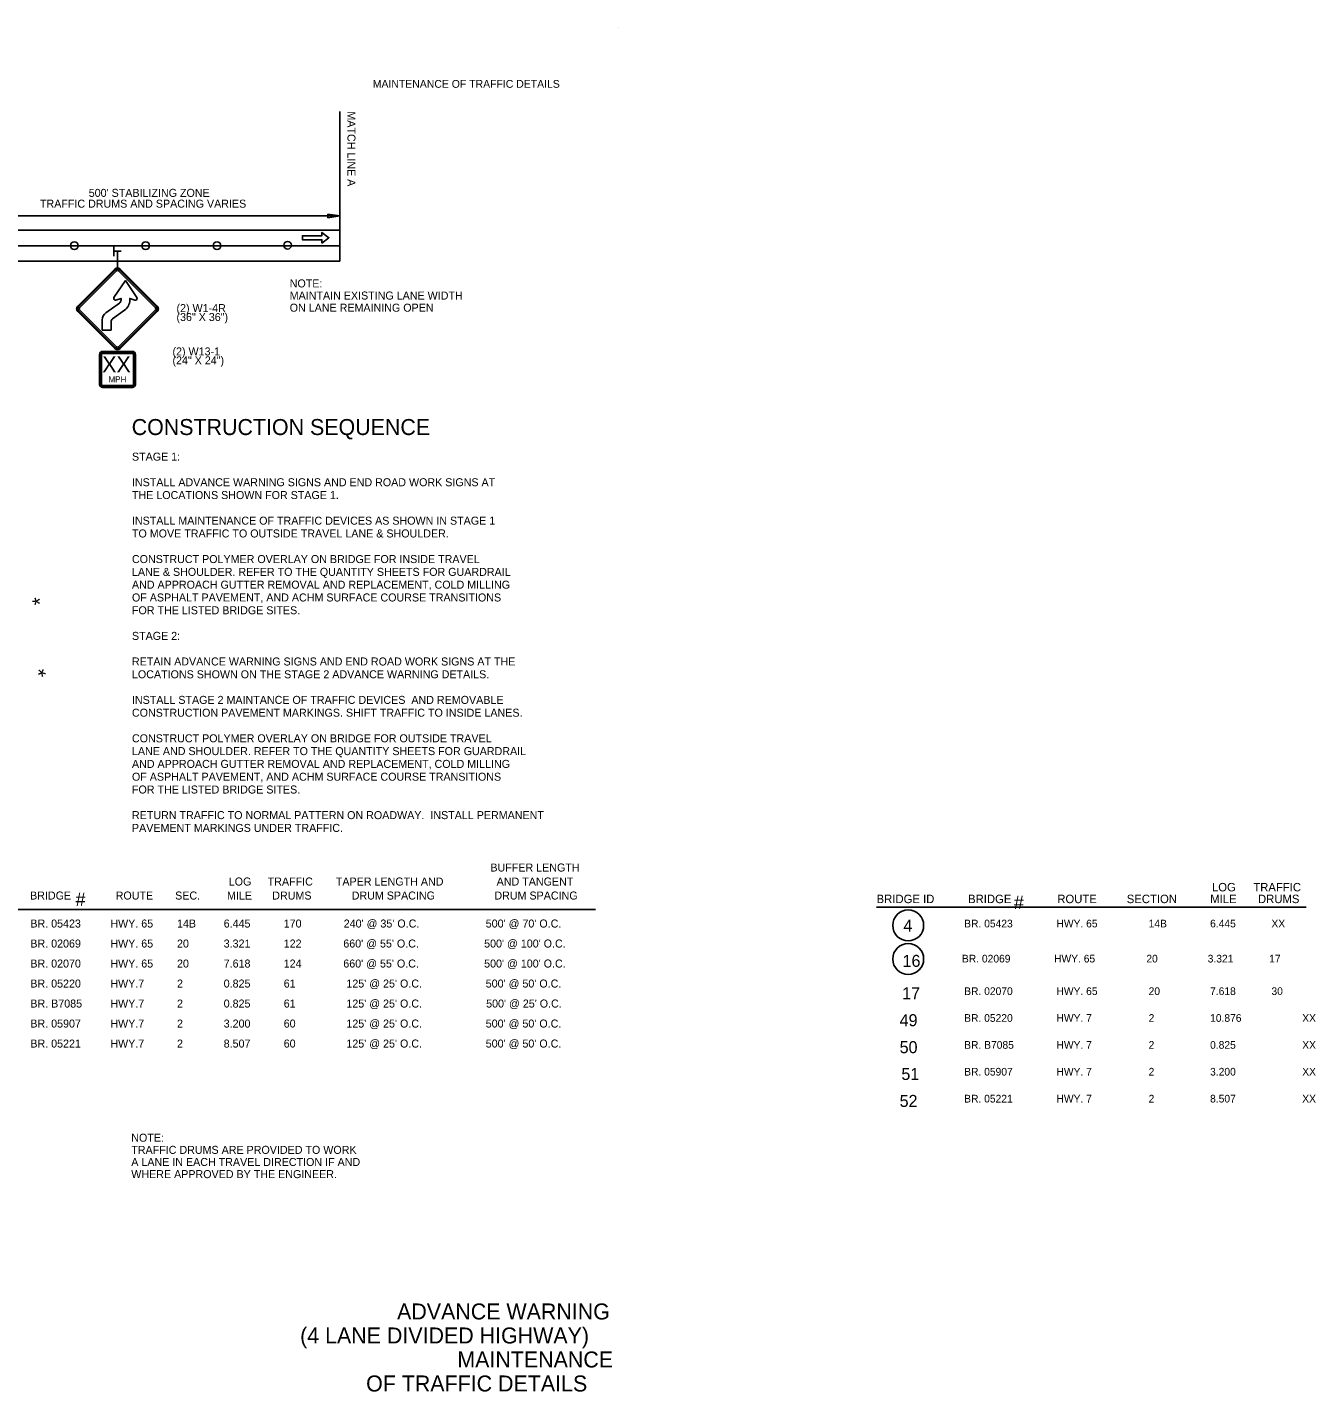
# Model space of a CAD drawing. Extents: x 1930579 to 1938745, y 596452 to 597559.
# Drawn here: x 1937779 to 1938745, y 596536 to 597559 of the extents above; entities that cross this region are included whole.
import ezdxf

# ---------------------------------------------------------------- set-up
doc = ezdxf.new("R2010")
doc.units = 0
for name, color, linetype in [('Default', 7, 'Continuous'), ('P_TC_Signs_Permanent', 7, 'Continuous'), ('R_Annotation', 7, 'Continuous'), ('R_Border', 7, 'Continuous'), ('R_Striping', 7, 'Continuous')]:
    doc.layers.add(name, color=color, linetype=linetype)

msp = doc.modelspace()

# ---------------------------------------------------------------- linework, layer by layer
at = {"layer": 'Default'}
for p, q in [((1938013.5, 597495.8), (1938013.5, 597383.6)), ((1938013.5, 597417.4), (1937761.7, 597417.4)), ((1938004.6, 597416.1), (1938004.6, 597418.8)), ((1938004.6, 597418.8), (1938013.5, 597417.4)), ((1938013.5, 597417.4), (1938004.6, 597416.1)), ((1938013.5, 597406.7), (1937394.5, 597406.7)), ((1938013.5, 597395.1), (1936726.8, 597395.1)), ((1937844, 597387.2), (1937844, 597395.1)), ((1938013.5, 597383.6), (1937394.5, 597383.6)), ((1937844.2, 597391.1), (1937849.6, 597391.1))]:
    msp.add_line(p, q, dxfattribs=at)
for centre, radius in [((1937814.5, 597395.1), 2.87), ((1937868, 597395.1), 2.87), ((1937921.5, 597395.1), 2.87), ((1937974.4, 597395.4), 2.87), ((1938439.8, 596885.4), 11.6), ((1938439.8, 596860.2), 11.6)]:
    msp.add_circle(centre, radius, dxfattribs=at)
at = {"layer": 'P_TC_Signs_Permanent'}
for p, q in [((1937817.1, 597349.8), (1937844.9, 597377.6)), ((1937817.6, 597349.2), (1937845.4, 597377.1)), ((1937846.2, 597376.3), (1937818.4, 597348.4)), ((1937875.4, 597348.4), (1937847.6, 597376.3)), ((1937848.3, 597377.1), (1937876.2, 597349.2)), ((1937848.9, 597377.6), (1937876.7, 597349.8)), ((1937838.1, 597344.7), (1937848.3, 597352.1)), ((1937844.9, 597318), (1937817.1, 597345.8)), ((1937845.4, 597318.5), (1937817.6, 597346.3)), ((1937818.4, 597347.1), (1937846.2, 597319.3)), ((1937852.2, 597346.7), (1937843.1, 597340.2)), ((1937847.6, 597319.3), (1937875.4, 597347.1)), ((1937876.2, 597346.3), (1937848.3, 597318.5)), ((1937876.7, 597345.8), (1937848.9, 597318)), ((1937833.4, 597313.6), (1937833.4, 597291.1)), ((1937834, 597313.6), (1937834, 597291.1)), ((1937834.9, 597313.6), (1937834.9, 597291.1)), ((1937858.1, 597315.8), (1937835.6, 597315.8)), ((1937858.1, 597315.3), (1937835.6, 597315.3)), ((1937858.1, 597314.3), (1937835.6, 597314.3)), ((1937858.9, 597291.1), (1937858.9, 597313.6)), ((1937859.8, 597291.1), (1937859.8, 597313.6)), ((1937860.4, 597291.1), (1937860.4, 597313.6)), ((1937835.6, 597290.3), (1937858.1, 597290.3)), ((1937835.6, 597289.4), (1937858.1, 597289.4)), ((1937835.6, 597288.8), (1937858.1, 597288.8))]:
    msp.add_line(p, q, dxfattribs=at)
for points in [[(1937844.2, 597356.3), (1937852.8, 597368.9), (1937861.4, 597356.3)], [(1937849.5, 597354.3), (1937849.5, 597355.5), (1937845.7, 597354.3)], [(1937859.9, 597354.3), (1937856.1, 597355.5), (1937856.1, 597354.3)], [(1937842, 597337.9), (1937842, 597331.8), (1937835.4, 597331.8), (1937835.4, 597339.4)]]:
    msp.add_lwpolyline(points, dxfattribs=at)
for centre, radius, start, end in [((1937846.9, 597375.6), 2.81, 45, 135), ((1937846.9, 597375.6), 2.06, 45, 135), ((1937846.9, 597375.6), 0.937, 45, 135), ((1937845.3, 597355.6), 1.31, 145.6763, 287.8128), ((1937846.7, 597354.3), 2.81, 305.7733, 0), ((1937846.7, 597354.3), 9.37, 305.7733, 0), ((1937860.3, 597355.6), 1.31, 252.1872, 34.3237), ((1937819, 597347.8), 2.81, 135, 225), ((1937819, 597347.8), 2.06, 135, 225), ((1937819, 597347.8), 0.937, 135, 225), ((1937842, 597339.4), 6.56, 125.7733, 180), ((1937844.8, 597337.9), 2.81, 125.7733, 180), ((1937874.7, 597347.8), 0.937, 315, 45), ((1937874.7, 597347.8), 2.06, 315, 45), ((1937874.7, 597347.8), 2.81, 315, 45), ((1937835.6, 597313.6), 2.25, 90, 180), ((1937835.6, 597313.6), 1.69, 90, 180), ((1937835.6, 597313.6), 0.75, 90, 180), ((1937846.9, 597319.9), 2.81, 225, 315), ((1937846.9, 597319.9), 2.06, 225, 315), ((1937846.9, 597319.9), 0.937, 225, 315), ((1937858.1, 597313.6), 2.25, 360, 90), ((1937858.1, 597313.6), 1.69, 360, 90), ((1937858.1, 597313.6), 0.75, 360, 90), ((1937835.6, 597291.1), 2.25, 180, 270), ((1937835.6, 597291.1), 1.69, 180, 270), ((1937835.6, 597291.1), 0.75, 180, 270), ((1937858.1, 597291.1), 2.25, 270, 360), ((1937858.1, 597291.1), 1.69, 270, 360), ((1937858.1, 597291.1), 0.75, 270, 360)]:
    msp.add_arc(centre, radius, start, end, dxfattribs=at)
at = {"layer": 'R_Annotation'}
for p, q in [((1937846.9, 597391.1), (1937846.9, 597378.4)), ((1937728.1, 596897.3), (1938205.3, 596897.3)), ((1938416.1, 596899.2), (1938738.3, 596899.2))]:
    msp.add_line(p, q, dxfattribs=at)
at = {"layer": 'R_Border'}
msp.add_line((1938222.3, 597558.9), (1938222.3, 597558.9), dxfattribs=at)
at = {"layer": 'R_Striping'}
msp.add_lwpolyline([(1938000.2, 597397), (1938005.4, 597401), (1938000.2, 597405), (1938000.2, 597402.5), (1937985.5, 597402.5), (1937985.5, 597399.5), (1938000.2, 597399.5)], close=True, dxfattribs=at)

# ---------------------------------------------------------------- texts
at = {"layer": 'Default'}
for s, rotation, p in [('MATCH LINE A', 270, (1938019.3, 597495.8)), ("500' STABILIZING ZONE", 360, (1937825.3, 597431.7)), ('TRAFFIC DRUMS AND SPACING VARIES', 360, (1937788.7, 597423.6))]:
    msp.add_text(s, height=6, rotation=rotation, dxfattribs=at).set_placement(p)
at = {"layer": 'P_TC_Signs_Permanent'}
for s, height, p in [('XX', 12, (1937835.4, 597300.1)), ('MPH', 4.5, (1937840.1, 597292.6))]:
    msp.add_text(s, height=height, rotation=360, dxfattribs=at).set_placement(p)
at = {"layer": 'R_Annotation'}
for s, height, rotation, p in [('NOTE:', 6, 360, (1937976, 597363.8)), ('MAINTAIN EXISTING LANE WIDTH ', 6, 360, (1937976, 597354.7)), ('(2) W1-4R', 6, 360, (1937891.1, 597345.3)), ('ON LANE REMAINING OPEN', 6, 360, (1937976, 597345.6)), ('(36" X 36")', 6, 360, (1937891.1, 597338.6)), ('(2) W13-1', 6, 360, (1937888.1, 597312.8)), ('(24" X 24")', 6, 360, (1937888.1, 597306.1)), ('CONSTRUCTION SEQUENCE', 12, 360, (1937857.5, 597253.1)), ('STAGE 1:', 6, 360, (1937857.7, 597233.9)), ('INSTALL ADVANCE WARNING SIGNS AND END ROAD WORK SIGNS AT', 6, 360, (1937857.7, 597214.7)), ('THE LOCATIONS SHOWN FOR STAGE 1.', 6, 360, (1937857.7, 597205.1)), ('INSTALL MAINTENANCE OF TRAFFIC DEVICES AS SHOWN IN STAGE 1', 6, 360, (1937857.7, 597185.9)), ('TO MOVE TRAFFIC TO OUTSIDE TRAVEL LANE & SHOULDER.', 6, 360, (1937857.7, 597176.3)), ('CONSTRUCT POLYMER OVERLAY ON BRIDGE FOR INSIDE TRAVEL', 6, 360, (1937857.7, 597157.1)), ('LANE & SHOULDER. REFER TO THE QUANTITY SHEETS FOR GUARDRAIL', 6, 360, (1937857.7, 597147.5)), ('AND APPROACH GUTTER REMOVAL AND REPLACEMENT, COLD MILLING', 6, 360, (1937857.7, 597137.9)), ('*', 11.5, 90.312, (1937794.4, 597125.5)), ('OF ASPHALT PAVEMENT, AND ACHM SURFACE COURSE TRANSITIONS', 6, 360, (1937857.7, 597128.3)), ('FOR THE LISTED BRIDGE SITES.', 6, 360, (1937857.7, 597118.7)), ('STAGE 2:', 6, 360, (1937857.7, 597099.5)), ('RETAIN ADVANCE WARNING SIGNS AND END ROAD WORK SIGNS AT THE', 6, 360, (1937857.7, 597080.3)), ('*', 11.5, 45, (1937793.9, 597066.7)), ('LOCATIONS SHOWN ON THE STAGE 2 ADVANCE WARNING DETAILS.', 6, 360, (1937857.7, 597070.7)), ('INSTALL STAGE 2 MAINTANCE OF TRAFFIC DEVICES  AND REMOVABLE', 6, 360, (1937857.7, 597051.5)), ('CONSTRUCTION PAVEMENT MARKINGS. SHIFT TRAFFIC TO INSIDE LANES.', 6, 360, (1937857.7, 597041.9)), ('CONSTRUCT POLYMER OVERLAY ON BRIDGE FOR OUTSIDE TRAVEL', 6, 360, (1937857.7, 597022.7)), ('LANE AND SHOULDER. REFER TO THE QUANTITY SHEETS FOR GUARDRAIL', 6, 360, (1937857.7, 597013.1)), ('AND APPROACH GUTTER REMOVAL AND REPLACEMENT, COLD MILLING', 6, 360, (1937857.7, 597003.5)), ('OF ASPHALT PAVEMENT, AND ACHM SURFACE COURSE TRANSITIONS', 6, 360, (1937857.7, 596993.9)), ('FOR THE LISTED BRIDGE SITES.', 6, 360, (1937857.7, 596984.3)), ('RETURN TRAFFIC TO NORMAL PATTERN ON ROADWAY.  INSTALL PERMANENT', 6, 360, (1937857.7, 596965.1)), ('PAVEMENT MARKINGS UNDER TRAFFIC.', 6, 360, (1937857.7, 596955.5)), ('LOG', 6, 360, (1937930.3, 596915.3)), ('TRAFFIC', 6, 360, (1937959.5, 596915.3)), ('TAPER LENGTH AND', 6, 360, (1938010.6, 596915.3)), ('BRIDGE', 6, 360, (1937781.3, 596904.8)), ('ROUTE', 6, 360, (1937845.5, 596904.8)), ('SEC.', 6, 360, (1937890.1, 596904.8)), ('MILE', 6, 360, (1937929, 596904.8)), ('DRUMS', 6, 360, (1937962.9, 596904.8)), ('DRUM SPACING', 6, 360, (1938022.5, 596904.8)), ('LOG', 6.34, 360, (1938667.6, 596910.9)), ('TRAFFIC', 6.34, 360, (1938698.6, 596910.9)), ('#', 10.1, 360, (1937815.4, 596899.9)), ('BRIDGE ID', 6.34, 360, (1938416.1, 596902.1)), ('BRIDGE ', 6.34, 360, (1938484.7, 596902.1)), ('#', 10.1, 360, (1938519, 596897.6)), ('ROUTE', 6.34, 360, (1938551.6, 596902.1)), ('SECTION', 6.34, 360, (1938603.7, 596902.1)), ('MILE', 6.34, 360, (1938666.3, 596902.1)), ('DRUMS', 6.34, 360, (1938702.1, 596902.1)), ('BR. 05423', 6, 360, (1937781.5, 596883.8)), ('HWY. 65', 6, 360, (1937841.5, 596883.8)), ('170', 6, 360, (1937971.5, 596883.8)), ("240' @ 35' O.C.", 6, 360, (1938016.5, 596883.8)), ('14B', 6, 360, (1937891.5, 596883.8)), ('4', 9, 360, (1938436.2, 596880.7)), ('BR. 05423', 5.76, 360, (1938481.8, 596883.9)), ('HWY. 65', 5.76, 360, (1938551, 596883.9)), ('14B', 5.76, 360, (1938620.1, 596883.9)), ('6.445', 5.76, 360, (1938666.2, 596883.9)), ('XX', 5.76, 360, (1938712.2, 596883.9)), ('BR. 02069', 6, 360, (1937781.5, 596868.8)), ('HWY. 65', 6, 360, (1937841.5, 596868.8)), ('20', 6, 360, (1937891.5, 596868.8)), ('122', 6, 360, (1937971.5, 596868.8)), ("660' @ 55' O.C.", 6, 360, (1938016.2, 596868.8)), ('BR. 02070', 6, 360, (1937781.5, 596853.8)), ('HWY. 65', 6, 360, (1937841.5, 596853.8)), ('20', 6, 360, (1937891.5, 596853.8)), ('124', 6, 360, (1937971.5, 596853.8)), ("660' @ 55' O.C.", 6, 360, (1938016.2, 596853.8)), ('16', 9, 360, (1938435.6, 596854.3)), ('BR. 02069', 5.76, 360, (1938480.1, 596857.6)), ('HWY. 65', 5.76, 360, (1938549.2, 596857.6)), ('20', 5.76, 360, (1938618.4, 596857.6)), ('3.321', 5.76, 360, (1938664.4, 596857.6)), ('17', 5.76, 360, (1938710.5, 596857.6)), ('BR. 05220', 6, 360, (1937781.5, 596838.8)), ('HWY.7', 6, 360, (1937841.5, 596838.8)), ('2', 6, 360, (1937891.5, 596838.8)), ('61', 6, 360, (1937971.5, 596838.8)), ("125' @ 25' O.C.", 6, 360, (1938018.5, 596838.8)), ('17', 9, 360, (1938435.3, 596830)), ('BR. 02070', 5.76, 360, (1938481.8, 596833.2)), ('HWY. 65', 5.76, 360, (1938551, 596833.2)), ('20', 5.76, 360, (1938620.1, 596833.2)), ('7.618', 5.76, 360, (1938666.2, 596833.2)), ('30', 5.76, 360, (1938712.2, 596833.2)), ('BR. B7085', 6, 360, (1937781.5, 596823.8)), ('HWY.7', 6, 360, (1937841.5, 596823.8)), ('2', 6, 360, (1937891.5, 596823.8)), ('61', 6, 360, (1937971.5, 596823.8)), ("125' @ 25' O.C.", 6, 360, (1938018.5, 596823.8)), ('49', 9, 360, (1938433.4, 596809.8)), ('BR. 05220', 5.76, 360, (1938481.8, 596813.1)), ('HWY. 7', 5.76, 360, (1938551, 596813.1)), ('2', 5.76, 360, (1938620.1, 596813.1)), ('10.876', 5.76, 360, (1938666.2, 596813.1)), ('XX', 5.76, 360, (1938735.3, 596813.1)), ('BR. 05907', 6, 360, (1937781.5, 596808.8)), ('HWY.7', 6, 360, (1937841.5, 596808.8)), ('2', 6, 360, (1937891.5, 596808.8)), ('60', 6, 360, (1937971.5, 596808.8)), ("125' @ 25' O.C.", 6, 360, (1938018.5, 596808.8)), ('BR. 05221', 6, 360, (1937781.5, 596793.8)), ('HWY.7', 6, 360, (1937841.5, 596793.8)), ('2', 6, 360, (1937891.5, 596793.8)), ('60', 6, 360, (1937971.5, 596793.8)), ("125' @ 25' O.C.", 6, 360, (1938018.5, 596793.8)), ('50', 9, 360, (1938433.4, 596789.6)), ('BR. B7085', 5.76, 360, (1938481.8, 596792.9)), ('HWY. 7', 5.76, 360, (1938551, 596792.9)), ('2', 5.76, 360, (1938620.1, 596792.9)), ('0.825', 5.76, 360, (1938666.2, 596792.9)), ('XX', 5.76, 360, (1938735.3, 596792.9)), ('51', 9, 360, (1938434.7, 596769.5)), ('BR. 05907', 5.76, 360, (1938481.8, 596772.8)), ('HWY. 7', 5.76, 360, (1938551, 596772.8)), ('2', 5.76, 360, (1938620.1, 596772.8)), ('3.200', 5.76, 360, (1938666.2, 596772.8)), ('XX', 5.76, 360, (1938735.3, 596772.8)), ('52', 9, 360, (1938433.4, 596749.3)), ('BR. 05221', 5.76, 360, (1938481.8, 596752.6)), ('HWY. 7', 5.76, 360, (1938551, 596752.6)), ('2', 5.76, 360, (1938620.1, 596752.6)), ('8.507', 5.76, 360, (1938666.2, 596752.6)), ('XX', 5.76, 360, (1938735.3, 596752.6)), ('NOTE:', 6, 360, (1937857.2, 596723.2)), ('TRAFFIC DRUMS ARE PROVIDED TO WORK', 6, 360, (1937857.2, 596714.1)), ('A LANE IN EACH TRAVEL DIRECTION IF AND', 6, 360, (1937857.2, 596705)), ('WHERE APPROVED BY THE ENGINEER.', 6, 360, (1937857.2, 596695.9)), ('ADVANCE WARNING ', 12, 360, (1938056.5, 596589.9)), ('(4 LANE DIVIDED HIGHWAY)', 12, 360, (1937983.8, 596571.9)), ('MAINTENANCE ', 12, 360, (1938101.7, 596553.9)), ('OF TRAFFIC DETAILS', 12, 360, (1938033.3, 596535.9))]:
    msp.add_text(s, height=height, rotation=rotation, dxfattribs=at).set_placement(p)
for s, p in [('BUFFER LENGTH', (1938126.5, 596925.8)), ('AND TANGENT', (1938131.2, 596915.3)), ('DRUM SPACING', (1938129.5, 596904.8)), ('6.445', (1937926.5, 596883.8)), ("500' @ 70' O.C.", (1938123, 596883.8)), ('3.321', (1937926.5, 596868.8)), ("500' @ 100' O.C.", (1938121.8, 596868.8)), ('7.618', (1937926.5, 596853.8)), ("500' @ 100' O.C.", (1938121.8, 596853.8)), ('0.825', (1937926.5, 596838.8)), ("500' @ 50' O.C.", (1938123, 596838.8)), ('0.825', (1937926.5, 596823.8)), ("500' @ 25' O.C.", (1938123.3, 596823.8)), ('3.200', (1937926.5, 596808.8)), ("500' @ 50' O.C.", (1938123, 596808.8)), ('8.507', (1937926.5, 596793.8)), ("500' @ 50' O.C.", (1938123, 596793.8))]:
    msp.add_text(s, height=6, dxfattribs=at).set_placement(p)
at = {"layer": 'R_Border'}
msp.add_text('MAINTENANCE OF TRAFFIC DETAILS', height=5.862, rotation=360, dxfattribs=at).set_placement((1938038.3, 597513.5))

doc.saveas('drawing.dxf')
